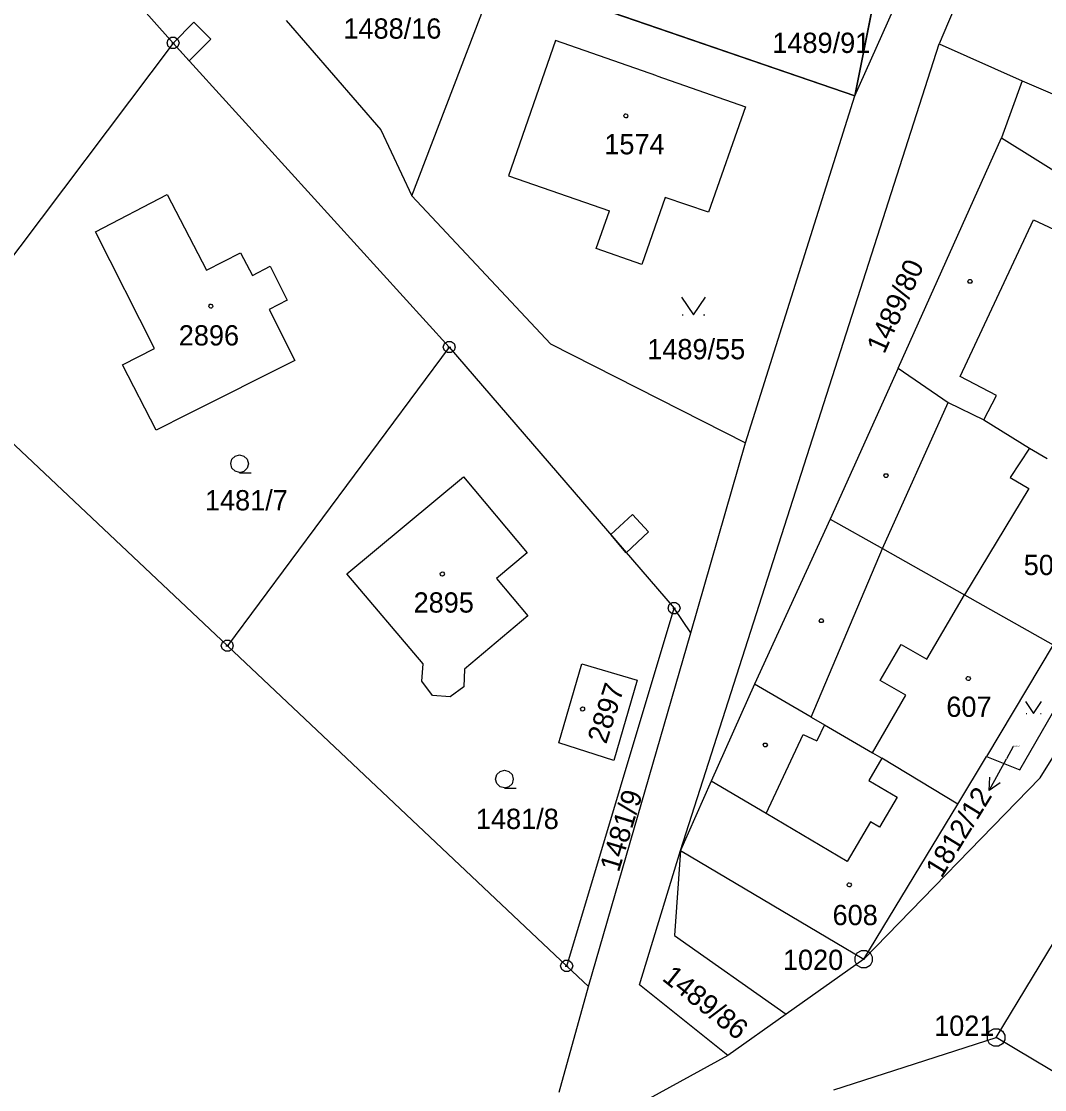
# Model space of a CAD drawing. Extents: x -779618 to -776429, y -1144546 to -1143350.
# Drawn here: x -777499.3 to -777413.5, y -1144217.4 to -1144127.7 of the extents above; entities that cross this region are included whole.
import ezdxf

# ---------------------------------------------------------------- set-up
doc = ezdxf.new("R2010")
doc.units = 0
for name, color, linetype in [('1', 7, 'Continuous'), ('11', 7, 'Continuous'), ('12', 7, 'Continuous'), ('13', 7, 'Continuous'), ('2', 7, 'Continuous'), ('3', 7, 'Continuous'), ('4', 7, 'Continuous'), ('5', 7, 'Continuous'), ('7', 7, 'Continuous'), ('8', 7, 'Continuous')]:
    doc.layers.add(name, color=color, linetype=linetype)

msp = doc.modelspace()

# ---------------------------------------------------------------- linework, layer by layer
at = {"layer": '1'}
for p, q in [((-777486.58, -1144129.52), (-777508.85, -1144104.39)), ((-777429.41, -1144133.96), (-777416.27, -1144104.56)), ((-777426.48, -1144119.18), (-777429.41, -1144133.96)), ((-777418.66, -1144120.82), (-777422.33, -1144129.58)), ((-777466.56, -1144142.33), (-777459.4, -1144123.62)), ((-777429.41, -1144133.96), (-777459.4, -1144123.62)), ((-777477.09, -1144127.63), (-777469.17, -1144136.79)), ((-777486.58, -1144129.52), (-777506.95, -1144156.58)), ((-777463.42, -1144155.04), (-777486.58, -1144129.52)), ((-777454.5, -1144129.31), (-777458.46, -1144140.66)), ((-777446.01, -1144132.26), (-777454.5, -1144129.31)), ((-777444.04, -1144197.28), (-777422.33, -1144129.58)), ((-777422.33, -1144129.58), (-777415.36, -1144132.69)), ((-777446.01, -1144132.26), (-777438.57, -1144134.86)), ((-777415.36, -1144132.69), (-777417.11, -1144137.48)), ((-777415.36, -1144132.69), (-777407.87, -1144135.93)), ((-777438.58, -1144163.08), (-777429.41, -1144133.96)), ((-777438.57, -1144134.86), (-777441.67, -1144143.71)), ((-777469.17, -1144136.79), (-777466.56, -1144142.33)), ((-777425.78, -1144156.8), (-777417.11, -1144137.48)), ((-777417.11, -1144137.48), (-777410.05, -1144141.88)), ((-777458.46, -1144140.66), (-777449.99, -1144143.61)), ((-777493.1, -1144145.35), (-777487.07, -1144142.22)), ((-777466.56, -1144142.33), (-777454.92, -1144154.76)), ((-777445.31, -1144142.49), (-777447.27, -1144148.11)), ((-777441.67, -1144143.71), (-777445.31, -1144142.49)), ((-777451.09, -1144146.76), (-777449.99, -1144143.61)), ((-777447.27, -1144148.11), (-777451.09, -1144146.76)), ((-777413.87, -1144191.2), (-777388.3, -1144149.96)), ((-777463.42, -1144155.04), (-777482.03, -1144180.11)), ((-777463.42, -1144155.04), (-777444.56, -1144176.95)), ((-777454.92, -1144154.76), (-777438.58, -1144163.08)), ((-777506.95, -1144156.58), (-777482.03, -1144180.11)), ((-777425.78, -1144156.8), (-777431.48, -1144169.48)), ((-777425.78, -1144156.8), (-777421.59, -1144159.68)), ((-777421.59, -1144159.68), (-777418.6, -1144161.15)), ((-777418.6, -1144161.15), (-777414.76, -1144163.52)), ((-777443.15, -1144179.01), (-777438.58, -1144163.08)), ((-777414.76, -1144163.52), (-777413.28, -1144164.38)), ((-777472.02, -1144174.06), (-777462.23, -1144165.92)), ((-777462.23, -1144165.92), (-777456.88, -1144172.3)), ((-777431.48, -1144169.48), (-777437.82, -1144183.33)), ((-777431.48, -1144169.48), (-777427.09, -1144171.95)), ((-777456.88, -1144172.3), (-777459.46, -1144174.47)), ((-777427.09, -1144171.95), (-777420.22, -1144175.82)), ((-777465.61, -1144181.63), (-777472.02, -1144174.06)), ((-777459.46, -1144174.47), (-777456.84, -1144177.59)), ((-777420.22, -1144175.82), (-777412.76, -1144180.02)), ((-777453.57, -1144206.98), (-777444.56, -1144176.95)), ((-777443.15, -1144179.01), (-777444.56, -1144176.95)), ((-777456.84, -1144177.59), (-777462.14, -1144182.06)), ((-777451.75, -1144208.7), (-777443.15, -1144179.01)), ((-777482.03, -1144180.11), (-777453.57, -1144206.98)), ((-777412.76, -1144180.02), (-777418.36, -1144189.4)), ((-777465.71, -1144183.08), (-777465.61, -1144181.63)), ((-777462.14, -1144182.06), (-777462.19, -1144183.54)), ((-777454.24, -1144188.24), (-777452.29, -1144181.61)), ((-777452.29, -1144181.61), (-777447.65, -1144182.99)), ((-777415.56, -1144190.52), (-777410.79, -1144182.2)), ((-777464.83, -1144184.28), (-777465.71, -1144183.08)), ((-777447.65, -1144182.99), (-777449.61, -1144189.74)), ((-777437.82, -1144183.33), (-777441.45, -1144191.48)), ((-777433.07, -1144186.09), (-777437.82, -1144183.33)), ((-777463.34, -1144184.4), (-777464.83, -1144184.28)), ((-777462.19, -1144183.54), (-777463.34, -1144184.4)), ((-777433.07, -1144186.09), (-777431.96, -1144186.74)), ((-777431.96, -1144186.74), (-777427.93, -1144189.08)), ((-777449.61, -1144189.74), (-777454.24, -1144188.24)), ((-777427.93, -1144189.08), (-777427.15, -1144189.55)), ((-777420.76, -1144193.41), (-777427.15, -1144189.55)), ((-777420.76, -1144193.41), (-777418.36, -1144189.4)), ((-777418.36, -1144189.4), (-777415.56, -1144190.52)), ((-777428.66, -1144206.41), (-777413.87, -1144191.2)), ((-777441.45, -1144191.48), (-777444.04, -1144197.28)), ((-777428.66, -1144206.41), (-777420.76, -1144193.41)), ((-777447.46, -1144208.55), (-777444.04, -1144197.28)), ((-777444.04, -1144197.28), (-777444.54, -1144204.42)), ((-777417.56, -1144212.98), (-777408.65, -1144198.25)), ((-777444.54, -1144204.42), (-777435.17, -1144211.02)), ((-777428.66, -1144206.41), (-777435.17, -1144211.02)), ((-777453.57, -1144206.98), (-777451.75, -1144208.7)), ((-777454.19, -1144217.58), (-777451.75, -1144208.7)), ((-777440.07, -1144214.48), (-777447.46, -1144208.55)), ((-777435.17, -1144211.02), (-777440.07, -1144214.48)), ((-777431.17, -1144217.38), (-777417.56, -1144212.98)), ((-777410.28, -1144217.33), (-777417.56, -1144212.98)), ((-777440.07, -1144214.48), (-777460.83, -1144225.9))]:
    msp.add_line(p, q, dxfattribs=at)
msp.add_lwpolyline([(-777487.07, -1144142.22), (-777483.77, -1144148.59), (-777480.92, -1144147.12), (-777479.93, -1144149.02), (-777478.43, -1144148.25), (-777477.01, -1144151.11), (-777478.52, -1144151.87), (-777476.37, -1144156.16), (-777485.34, -1144160.67), (-777487.99, -1144162), (-777490.83, -1144156.53), (-777488.14, -1144155.16), (-777493.1, -1144145.35)], dxfattribs=at)
at = {"layer": '11'}
msp.add_lwpolyline([(-777424.75, -1144115.22), (-777418.35, -1144100.63), (-777415.31, -1144091.05), (-777414.48, -1144080.94), (-777426.9, -1144081.28), (-777427.33, -1144077.27), (-777428.5, -1144077.41), (-777428.53, -1144080.55), (-777436.26, -1144080.64), (-777436.33, -1144078.38), (-777436.36, -1144077.31), (-777439.75, -1144077.36), (-777444.27, -1144081.27), (-777444.56, -1144082.09), (-777449.21, -1144095.09), (-777454.4, -1144109.61), (-777459.4, -1144123.62), (-777429.41, -1144133.96), (-777426.48, -1144119.18)], close=True, dxfattribs=at)
at = {"layer": '12'}
for p, q in [((-777418.66, -1144120.82), (-777422.33, -1144129.58)), ((-777454.5, -1144129.31), (-777458.46, -1144140.66)), ((-777446.01, -1144132.26), (-777454.5, -1144129.31)), ((-777422.33, -1144129.58), (-777415.36, -1144132.69)), ((-777446.01, -1144132.26), (-777438.57, -1144134.86)), ((-777415.36, -1144132.69), (-777407.87, -1144135.93)), ((-777438.57, -1144134.86), (-777441.67, -1144143.71)), ((-777458.46, -1144140.66), (-777449.99, -1144143.61)), ((-777493.1, -1144145.35), (-777487.07, -1144142.22)), ((-777445.31, -1144142.49), (-777447.27, -1144148.11)), ((-777441.67, -1144143.71), (-777445.31, -1144142.49)), ((-777451.09, -1144146.76), (-777449.99, -1144143.61)), ((-777447.27, -1144148.11), (-777451.09, -1144146.76)), ((-777414.76, -1144163.52), (-777416.37, -1144165.97)), ((-777414.76, -1144163.52), (-777413.28, -1144164.38)), ((-777472.02, -1144174.06), (-777462.23, -1144165.92)), ((-777462.23, -1144165.92), (-777456.88, -1144172.3)), ((-777416.37, -1144165.97), (-777414.82, -1144166.91)), ((-777414.82, -1144166.91), (-777420.22, -1144175.82)), ((-777456.88, -1144172.3), (-777459.46, -1144174.47)), ((-777465.61, -1144181.63), (-777472.02, -1144174.06)), ((-777459.46, -1144174.47), (-777456.84, -1144177.59)), ((-777423.37, -1144181.24), (-777420.22, -1144175.82)), ((-777420.22, -1144175.82), (-777412.76, -1144180.02)), ((-777420.22, -1144175.82), (-777412.76, -1144180.02)), ((-777456.84, -1144177.59), (-777462.14, -1144182.06)), ((-777427.28, -1144183.01), (-777425.53, -1144179.99)), ((-777425.53, -1144179.99), (-777423.37, -1144181.24)), ((-777412.76, -1144180.02), (-777418.36, -1144189.4)), ((-777465.71, -1144183.08), (-777465.61, -1144181.63)), ((-777462.14, -1144182.06), (-777462.19, -1144183.54)), ((-777454.24, -1144188.24), (-777452.29, -1144181.61)), ((-777452.29, -1144181.61), (-777447.65, -1144182.99)), ((-777464.83, -1144184.28), (-777465.71, -1144183.08)), ((-777447.65, -1144182.99), (-777449.61, -1144189.74)), ((-777425.13, -1144184.26), (-777427.28, -1144183.01)), ((-777463.34, -1144184.4), (-777464.83, -1144184.28)), ((-777462.19, -1144183.54), (-777463.34, -1144184.4)), ((-777427.93, -1144189.08), (-777425.13, -1144184.26)), ((-777449.61, -1144189.74), (-777454.24, -1144188.24)), ((-777427.15, -1144189.55), (-777428.22, -1144191.42)), ((-777427.93, -1144189.08), (-777427.15, -1144189.55)), ((-777420.76, -1144193.41), (-777427.15, -1144189.55)), ((-777420.76, -1144193.41), (-777427.15, -1144189.55)), ((-777420.76, -1144193.41), (-777418.36, -1144189.4)), ((-777428.22, -1144191.42), (-777425.85, -1144192.82)), ((-777441.45, -1144191.48), (-777444.04, -1144197.28)), ((-777436.85, -1144194.19), (-777441.45, -1144191.48)), ((-777425.85, -1144192.82), (-777427.33, -1144195.33)), ((-777428.66, -1144206.41), (-777420.76, -1144193.41)), ((-777430.04, -1144198.21), (-777436.85, -1144194.19)), ((-777428.08, -1144194.89), (-777430.04, -1144198.21)), ((-777427.33, -1144195.33), (-777428.08, -1144194.89)), ((-777444.04, -1144197.28), (-777428.66, -1144206.41)), ((-777417.56, -1144212.98), (-777408.65, -1144198.25)), ((-777410.28, -1144217.33), (-777417.56, -1144212.98))]:
    msp.add_line(p, q, dxfattribs=at)
msp.add_lwpolyline([(-777487.07, -1144142.22), (-777483.77, -1144148.59), (-777480.92, -1144147.12), (-777479.93, -1144149.02), (-777478.43, -1144148.25), (-777477.01, -1144151.11), (-777478.52, -1144151.87), (-777476.37, -1144156.16), (-777485.34, -1144160.67), (-777487.99, -1144162), (-777490.83, -1144156.53), (-777488.14, -1144155.16), (-777493.1, -1144145.35)], dxfattribs=at)
at = {"layer": '13'}
for p, q in [((-777486.58, -1144129.52), (-777484.84, -1144127.77)), ((-777484.84, -1144127.77), (-777483.41, -1144129.19)), ((-777485.22, -1144131.02), (-777486.58, -1144129.52)), ((-777483.41, -1144129.19), (-777485.22, -1144131.02)), ((-777449.88, -1144170.77), (-777448.06, -1144169.08)), ((-777448.06, -1144169.08), (-777446.7, -1144170.54)), ((-777448.58, -1144172.29), (-777449.88, -1144170.77)), ((-777446.7, -1144170.54), (-777448.58, -1144172.29))]:
    msp.add_line(p, q, dxfattribs=at)
at = {"layer": '3'}
for p, q in [((-777443.89, -1144152.34), (-777443.79, -1144152.34)), ((-777442.09, -1144152.34), (-777441.99, -1144152.34)), ((-777415.046, -1144185.79), (-777414.98, -1144185.79)), ((-777413.841, -1144185.79), (-777413.774, -1144185.79))]:
    msp.add_line(p, q, dxfattribs=at)
for points in [[(-777443.94, -1144150.84), (-777442.94, -1144152.34), (-777441.94, -1144150.84)], [(-777481, -1144165.56), (-777481.38, -1144165.46), (-777481.65, -1144165.19), (-777481.75, -1144164.82), (-777481.65, -1144164.45), (-777481.38, -1144164.18), (-777481.01, -1144164.08), (-777480.64, -1144164.18), (-777480.37, -1144164.45), (-777480.27, -1144164.83), (-777480.37, -1144165.21), (-777480.64, -1144165.48), (-777481.02, -1144165.58), (-777480.02, -1144165.58)], [(-777415.08, -1144184.785), (-777414.41, -1144185.79), (-777413.74, -1144184.785)], [(-777458.78, -1144192.03), (-777459.16, -1144191.93), (-777459.43, -1144191.66), (-777459.53, -1144191.29), (-777459.43, -1144190.92), (-777459.16, -1144190.65), (-777458.79, -1144190.55), (-777458.42, -1144190.65), (-777458.15, -1144190.92), (-777458.05, -1144191.3), (-777458.15, -1144191.68), (-777458.42, -1144191.95), (-777458.8, -1144192.05), (-777457.8, -1144192.05)]]:
    msp.add_lwpolyline(points, dxfattribs=at)
at = {"layer": '4'}
for p, q in [((-777420.57, -1144157.51), (-777414.42, -1144144.35)), ((-777414.42, -1144144.35), (-777411.84, -1144145.56)), ((-777417.53, -1144159.11), (-777420.57, -1144157.51)), ((-777418.6, -1144161.15), (-777417.53, -1144159.11)), ((-777427.09, -1144171.95), (-777421.59, -1144159.68)), ((-777414.76, -1144163.52), (-777416.37, -1144165.97)), ((-777416.37, -1144165.97), (-777414.82, -1144166.91)), ((-777414.82, -1144166.91), (-777420.22, -1144175.82)), ((-777433.07, -1144186.09), (-777427.09, -1144171.95)), ((-777423.37, -1144181.24), (-777420.22, -1144175.82)), ((-777427.28, -1144183.01), (-777425.53, -1144179.99)), ((-777425.53, -1144179.99), (-777423.37, -1144181.24)), ((-777425.13, -1144184.26), (-777427.28, -1144183.01)), ((-777427.93, -1144189.08), (-777425.13, -1144184.26)), ((-777431.96, -1144186.74), (-777432.59, -1144188.09)), ((-777436.85, -1144194.19), (-777433.75, -1144187.55)), ((-777433.75, -1144187.55), (-777432.59, -1144188.09)), ((-777427.15, -1144189.55), (-777428.22, -1144191.42)), ((-777428.22, -1144191.42), (-777425.85, -1144192.82)), ((-777436.85, -1144194.19), (-777441.45, -1144191.48)), ((-777425.85, -1144192.82), (-777427.33, -1144195.33)), ((-777430.04, -1144198.21), (-777436.85, -1144194.19)), ((-777428.08, -1144194.89), (-777430.04, -1144198.21)), ((-777427.33, -1144195.33), (-777428.08, -1144194.89)), ((-777444.04, -1144197.28), (-777428.66, -1144206.41))]:
    msp.add_line(p, q, dxfattribs=at)
at = {"layer": '5'}
for points in [[(-777448.61, -1144135.46), (-777448.51, -1144135.48), (-777448.46, -1144135.57), (-777448.44, -1144135.63), (-777448.46, -1144135.72), (-777448.54, -1144135.79), (-777448.61, -1144135.8), (-777448.7, -1144135.77), (-777448.76, -1144135.71), (-777448.78, -1144135.63), (-777448.76, -1144135.54), (-777448.68, -1144135.47)], [(-777419.66, -1144149.37), (-777419.57, -1144149.52), (-777419.66, -1144149.67), (-777419.84, -1144149.67), (-777419.93, -1144149.52), (-777419.84, -1144149.37)], [(-777483.42, -1144151.43), (-777483.32, -1144151.45), (-777483.27, -1144151.54), (-777483.25, -1144151.6), (-777483.27, -1144151.69), (-777483.35, -1144151.76), (-777483.42, -1144151.77), (-777483.51, -1144151.74), (-777483.57, -1144151.68), (-777483.59, -1144151.6), (-777483.57, -1144151.51), (-777483.49, -1144151.44)], [(-777426.7, -1144165.67), (-777426.61, -1144165.82), (-777426.7, -1144165.97), (-777426.88, -1144165.97), (-777426.97, -1144165.82), (-777426.88, -1144165.67)], [(-777464, -1144173.91), (-777463.9, -1144173.93), (-777463.85, -1144174.02), (-777463.83, -1144174.08), (-777463.85, -1144174.17), (-777463.93, -1144174.24), (-777464, -1144174.25), (-777464.09, -1144174.22), (-777464.15, -1144174.16), (-777464.17, -1144174.08), (-777464.15, -1144173.99), (-777464.07, -1144173.92)], [(-777432.13, -1144177.85), (-777432.04, -1144178), (-777432.13, -1144178.15), (-777432.31, -1144178.15), (-777432.4, -1144178), (-777432.31, -1144177.85)], [(-777419.89, -1144182.68), (-777419.79, -1144182.7), (-777419.74, -1144182.79), (-777419.72, -1144182.85), (-777419.74, -1144182.94), (-777419.82, -1144183.01), (-777419.89, -1144183.02), (-777419.98, -1144182.99), (-777420.04, -1144182.93), (-777420.06, -1144182.85), (-777420.04, -1144182.76), (-777419.96, -1144182.69)], [(-777452.24, -1144185.24), (-777452.14, -1144185.26), (-777452.09, -1144185.35), (-777452.07, -1144185.41), (-777452.09, -1144185.5), (-777452.17, -1144185.57), (-777452.24, -1144185.58), (-777452.33, -1144185.55), (-777452.39, -1144185.49), (-777452.41, -1144185.41), (-777452.39, -1144185.32), (-777452.31, -1144185.25)], [(-777436.83, -1144188.28), (-777436.74, -1144188.43), (-777436.83, -1144188.58), (-777437.01, -1144188.58), (-777437.1, -1144188.43), (-777437.01, -1144188.28)], [(-777429.87, -1144200), (-777429.77, -1144200.02), (-777429.72, -1144200.11), (-777429.7, -1144200.17), (-777429.72, -1144200.26), (-777429.8, -1144200.33), (-777429.87, -1144200.34), (-777429.96, -1144200.31), (-777430.02, -1144200.25), (-777430.04, -1144200.17), (-777430.02, -1144200.08), (-777429.94, -1144200.01)]]:
    msp.add_lwpolyline(points, close=True, dxfattribs=at)
at = {"layer": '7'}
for p in [(-777416.13, -1144188.56), (-777418.132, -1144192.236)]:
    msp.add_line(p, (-777416.7, -1144189.6), dxfattribs=at)
msp.add_lwpolyline([(-777417.215, -1144191.596), (-777418.132, -1144192.236), (-777418.094, -1144191.119)], dxfattribs=at)
at = {"layer": '8'}
for p, q in [((-777486.7, -1144129.52), (-777486.46, -1144129.52)), ((-777463.54, -1144155.04), (-777463.3, -1144155.04)), ((-777444.68, -1144176.95), (-777444.44, -1144176.95)), ((-777482.15, -1144180.11), (-777481.91, -1144180.11)), ((-777428.71, -1144206.41), (-777428.61, -1144206.41)), ((-777453.69, -1144206.98), (-777453.45, -1144206.98)), ((-777417.61, -1144212.98), (-777417.51, -1144212.98))]:
    msp.add_line(p, q, dxfattribs=at)
for points in [[(-777486.43, -1144129.04), (-777486.18, -1144129.22), (-777486.08, -1144129.51), (-777486.18, -1144129.8), (-777486.43, -1144129.98), (-777486.74, -1144129.98), (-777486.99, -1144129.8), (-777487.09, -1144129.51), (-777486.99, -1144129.22), (-777486.74, -1144129.04)], [(-777463.27, -1144154.56), (-777463.02, -1144154.74), (-777462.92, -1144155.03), (-777463.02, -1144155.32), (-777463.27, -1144155.5), (-777463.58, -1144155.5), (-777463.83, -1144155.32), (-777463.93, -1144155.03), (-777463.83, -1144154.74), (-777463.58, -1144154.56)], [(-777444.41, -1144176.47), (-777444.16, -1144176.65), (-777444.06, -1144176.94), (-777444.16, -1144177.23), (-777444.41, -1144177.41), (-777444.72, -1144177.41), (-777444.97, -1144177.23), (-777445.07, -1144176.94), (-777444.97, -1144176.65), (-777444.72, -1144176.47)], [(-777481.88, -1144179.63), (-777481.63, -1144179.81), (-777481.53, -1144180.1), (-777481.63, -1144180.39), (-777481.88, -1144180.57), (-777482.19, -1144180.57), (-777482.44, -1144180.39), (-777482.54, -1144180.1), (-777482.44, -1144179.81), (-777482.19, -1144179.63)], [(-777428.47, -1144205.69), (-777428.13, -1144205.88), (-777427.94, -1144206.22), (-777427.94, -1144206.61), (-777428.13, -1144206.95), (-777428.47, -1144207.14), (-777428.86, -1144207.14), (-777429.2, -1144206.95), (-777429.39, -1144206.61), (-777429.39, -1144206.22), (-777429.2, -1144205.88), (-777428.86, -1144205.69)], [(-777453.42, -1144206.5), (-777453.17, -1144206.68), (-777453.07, -1144206.97), (-777453.17, -1144207.26), (-777453.42, -1144207.44), (-777453.73, -1144207.44), (-777453.98, -1144207.26), (-777454.08, -1144206.97), (-777453.98, -1144206.68), (-777453.73, -1144206.5)], [(-777417.37, -1144212.26), (-777417.03, -1144212.45), (-777416.84, -1144212.79), (-777416.84, -1144213.18), (-777417.03, -1144213.52), (-777417.37, -1144213.71), (-777417.76, -1144213.71), (-777418.1, -1144213.52), (-777418.29, -1144213.18), (-777418.29, -1144212.79), (-777418.1, -1144212.45), (-777417.76, -1144212.26)]]:
    msp.add_lwpolyline(points, close=True, dxfattribs=at)

# ---------------------------------------------------------------- texts
at = {"layer": '2'}
for s, height, p in [('1488/16', 1.7, (-777472.297, -1144129.15)), ('1489/91', 1.7, (-777436.327, -1144130.35)), ('1574', 1.7, (-777450.417, -1144138.86)), ('2896', 1.7, (-777486.104, -1144154.9)), ('1489/55', 1.7, (-777446.817, -1144156.06)), ('1481/7', 1.7, (-777483.913, -1144168.74)), ('503', 1.7, (-777415.243, -1144174.17)), ('2895', 1.7, (-777466.413, -1144177.32)), ('607', 1.7, (-777421.733, -1144186.07)), ('1812/12', 0.1, (-777416.107, -1144188.56)), ('1481/8', 1.7, (-777461.187, -1144195.48)), ('608', 1.7, (-777431.273, -1144203.55))]:
    msp.add_text(s, height=height, dxfattribs=at).set_placement(p)
for s, rotation, p in [('1489/80', 65.77555, (-777426.939, -1144155.682)), ('2897', 72.24998, (-777450.258, -1144188.414)), ('1481/9', 73.10941, (-777449.206, -1144199.174)), ('1489/86', 321.31473, (-777445.653, -1144208.125))]:
    msp.add_text(s, height=1.7, rotation=rotation, dxfattribs=at).set_placement(p)
at = {"layer": '7'}
msp.add_text('1812/12', height=1.7, rotation=58.49899, dxfattribs=at).set_placement((-777422.134, -1144199.673))
at = {"layer": '8'}
for s, p in [('1020', (-777435.437, -1144207.31)), ('1021', (-777422.757, -1144212.84))]:
    msp.add_text(s, height=1.7, dxfattribs=at).set_placement(p)

doc.saveas('drawing.dxf')
